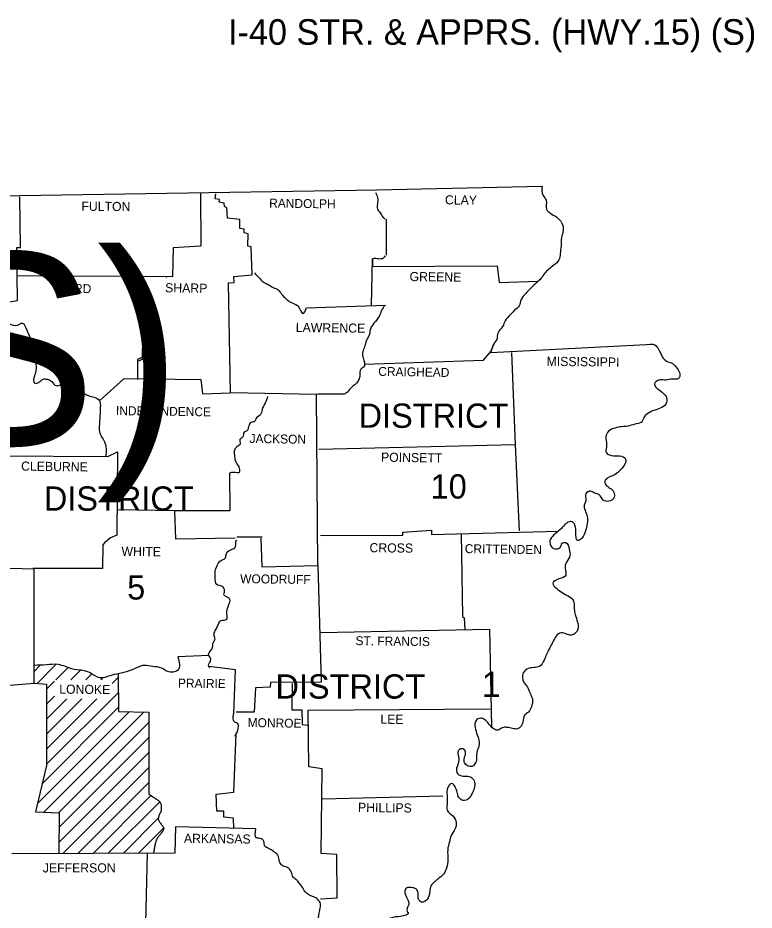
# Model space of a CAD drawing. Extents: x 1127717 to 1741049, y 2026793 to 2244711.
# Drawn here: x 1371845 to 1389121, y 2132784 to 2153727 of the extents above; entities that cross this region are included whole.
import ezdxf

# ---------------------------------------------------------------- set-up
doc = ezdxf.new("R2010")
doc.units = 0
doc.layers.add('1', color=7, linetype='Continuous')
doc.layers.add('R_Draft', color=7, linetype='Continuous')

msp = doc.modelspace()

# ---------------------------------------------------------------- linework, layer by layer
at = {"layer": 'R_Draft'}
for p, q in [((1380455, 2146979), (1380470, 2146984)), ((1382945, 2145874), (1383005, 2146059)), ((1382960, 2145934), (1383020, 2146079)), ((1376985, 2141544), (1377580, 2141544)), ((1372225, 2138388), (1372371, 2138534)), ((1372295, 2138105), (1372738, 2138548)), ((1372736, 2138192), (1373023, 2138480)), ((1373089, 2138192), (1373314, 2138417)), ((1373443, 2138192), (1373582, 2138331)), ((1372515, 2137971), (1372704, 2138160)), ((1373796, 2138192), (1373848, 2138243)), ((1374060, 2138102), (1374201, 2138243)), ((1372520, 2136208), (1374205, 2137893)), ((1372516, 2137619), (1372704, 2137807)), ((1372517, 2137266), (1372993, 2137742)), ((1372518, 2136914), (1373346, 2137742)), ((1372519, 2136561), (1373700, 2137742)), ((1372306, 2135287), (1374458, 2137439)), ((1372417, 2135752), (1374209, 2137544)), ((1372458, 2135086), (1374804, 2137432)), ((1372796, 2135070), (1374915, 2137190)), ((1372813, 2134734), (1374916, 2136837)), ((1372811, 2134378), (1374917, 2136484)), ((1372900, 2134114), (1374918, 2136132)), ((1373255, 2134116), (1374919, 2135779)), ((1373610, 2134117), (1374969, 2135476)), ((1373965, 2134118), (1375173, 2135326)), ((1374320, 2134120), (1375141, 2134940)), ((1374675, 2134121), (1375268, 2134714)), ((1375030, 2134122), (1375031, 2134123))]:
    msp.add_line(p, q, dxfattribs=at)
for points in [[(1356715, 2149549), (1364800, 2149544), (1371895, 2149559), (1380265, 2149689), (1384145, 2149779)], [(1376130, 2149604), (1376140, 2148364), (1375490, 2148329), (1375470, 2147649), (1371855, 2147669)], [(1377545, 2141514), (1377570, 2140839), (1378885, 2140874), (1378850, 2144884), (1376835, 2144929), (1376790, 2147509), (1376920, 2147514), (1376915, 2147654), (1377340, 2147694), (1377320, 2148349), (1377240, 2148364), (1377245, 2148654), (1377155, 2148679), (1377155, 2148764), (1377050, 2148779), (1377050, 2148994), (1376765, 2149024), (1376750, 2149264), (1376695, 2149299), (1376685, 2149379), (1376570, 2149404), (1376575, 2149464), (1376475, 2149479), (1376490, 2149599)], [(1370380, 2137464), (1371505, 2137469), (1371555, 2138059), (1372225, 2138109), (1372225, 2140789), (1371375, 2140814), (1371390, 2143449), (1370320, 2143519), (1370305, 2144699), (1370270, 2144759), (1370300, 2145499), (1370920, 2145519), (1370945, 2146129), (1371625, 2146154), (1371635, 2146549), (1371515, 2146704), (1371485, 2147039), (1371835, 2147089), (1371820, 2148334), (1371905, 2148339), (1371895, 2149529)], [(1380485, 2148999), (1380485, 2148154)], [(1380143, 2146973), (1380170, 2148074), (1380170, 2147889), (1383095, 2147904), (1383135, 2147514), (1384053, 2147548)], [(1374700, 2147634), (1374690, 2147344), (1374830, 2147334), (1374835, 2147014), (1374785, 2147014), (1374765, 2145754), (1374650, 2145704), (1374650, 2145284)], [(1374700, 2147589), (1374690, 2147299), (1374830, 2147289), (1374835, 2146969), (1374785, 2146969), (1374765, 2145709), (1374650, 2145659), (1374650, 2145239)], [(1375325, 2147624), (1375330, 2147629)], [(1378615, 2146919), (1380470, 2146984)], [(1382945, 2145874), (1386740, 2146069)], [(1379970, 2145599), (1382770, 2145689), (1382953, 2145901)], [(1383425, 2145869), (1383510, 2143704), (1383610, 2141689)], [(1373770, 2144749), (1374340, 2145264), (1376140, 2145239), (1376175, 2144904), (1376830, 2144929)], [(1379505, 2144894), (1378895, 2144894), (1378850, 2144884)], [(1371390, 2143449), (1373960, 2143434), (1374180, 2143539), (1374165, 2141584), (1374015, 2141519), (1373880, 2141404), (1373835, 2141359), (1373830, 2140799), (1372195, 2140799)], [(1383510, 2143704), (1378905, 2143599)], [(1376810, 2143039), (1376820, 2142159), (1375520, 2142154), (1374185, 2142179)], [(1375520, 2142154), (1375540, 2141499), (1376945, 2141524)], [(1378945, 2141574), (1380875, 2141584), (1380880, 2141654), (1381550, 2141704), (1381550, 2141599), (1384528, 2141681)], [(1376985, 2141459), (1376960, 2141454)], [(1382249, 2141619), (1382275, 2139674), (1382320, 2139644), (1382336, 2139368)], [(1378885, 2140874), (1378960, 2138134), (1377770, 2138129), (1377765, 2138019), (1377420, 2137999), (1377390, 2137429), (1376970, 2137429)], [(1378945, 2139299), (1382915, 2139379)], [(1382915, 2139379), (1382957, 2137089)], [(1376325, 2138764), (1375600, 2138729)], [(1376915, 2137404), (1376950, 2138424), (1376325, 2138504)], [(1374200, 2138333), (1374210, 2137444), (1374915, 2137429), (1374920, 2135509)], [(1372225, 2138109), (1372515, 2138089), (1372520, 2136179), (1372260, 2135094), (1372815, 2135069), (1372810, 2134114)], [(1378280, 2138104), (1378275, 2137484), (1378505, 2137484), (1378515, 2137139), (1378660, 2137124)], [(1378945, 2133049), (1379335, 2133074), (1379330, 2134089), (1378965, 2134114), (1378985, 2136099), (1378670, 2136144), (1378660, 2137479), (1382925, 2137509)], [(1376912, 2134703), (1376905, 2134944), (1376680, 2134969), (1376675, 2135109), (1376510, 2135104), (1376500, 2135509), (1376910, 2135554), (1376970, 2136924)], [(1378995, 2135394), (1381815, 2135464)], [(1377430, 2134689), (1375540, 2134739), (1375530, 2134124), (1371705, 2134109)], [(1374876, 2134122), (1374835, 2132159), (1375530, 2132104)]]:
    msp.add_lwpolyline(points, dxfattribs=at)
for points in [[(1380240, 2149624), (1380285, 2149499), (1380280, 2149364), (1380280, 2149239), (1380345, 2149154), (1380410, 2149049), (1380460, 2149004)], [(1384145, 2149779), (1384170, 2149559), (1384240, 2149444), (1384250, 2149234), (1384335, 2149144), (1384480, 2149054), (1384610, 2148909), (1384640, 2148739), (1384600, 2148564), (1384590, 2148369), (1384570, 2148199), (1384540, 2148044), (1384420, 2147919), (1384305, 2147829), (1384200, 2147724), (1384125, 2147614), (1383995, 2147494), (1383865, 2147369), (1383760, 2147259), (1383655, 2147119), (1383605, 2146964), (1383490, 2146854), (1383400, 2146754), (1383280, 2146619), (1383220, 2146484), (1383105, 2146329), (1383080, 2146179), (1383005, 2146059), (1383000, 2146039)], [(1384145, 2149779), (1384170, 2149559), (1384240, 2149444), (1384250, 2149234), (1384335, 2149144), (1384480, 2149054), (1384610, 2148909), (1384640, 2148739), (1384600, 2148564), (1384590, 2148369), (1384570, 2148199), (1384540, 2148044), (1384420, 2147919), (1384305, 2147829), (1384200, 2147724), (1384125, 2147614), (1383995, 2147494), (1383865, 2147369), (1383760, 2147259), (1383655, 2147119), (1383605, 2146964), (1383490, 2146854), (1383400, 2146754), (1383280, 2146619), (1383220, 2146484), (1383105, 2146329), (1383080, 2146179), (1383005, 2146059), (1383000, 2146039)], [(1380465, 2148139), (1380400, 2148074), (1380275, 2148074), (1380170, 2148074)], [(1377395, 2147739), (1377505, 2147624), (1377600, 2147529), (1377710, 2147474), (1377840, 2147399), (1377955, 2147339), (1378030, 2147244), (1378135, 2147139), (1378240, 2147054), (1378405, 2146974), (1378460, 2146889), (1378535, 2146784), (1378615, 2146919)], [(1380455, 2146979), (1380380, 2146859), (1380320, 2146719), (1380200, 2146559), (1380110, 2146404), (1380095, 2146299), (1380025, 2146159), (1379985, 2146019), (1379940, 2145899), (1379940, 2145774), (1379975, 2145649), (1379965, 2145534), (1379890, 2145479), (1379870, 2145334), (1379840, 2145234), (1379775, 2145134), (1379680, 2145059), (1379580, 2144944), (1379505, 2144894)], [(1371635, 2146549), (1371835, 2146514), (1371955, 2146559), (1372040, 2146429), (1372085, 2146329), (1372160, 2146184), (1372280, 2146139), (1372370, 2146059), (1372370, 2145974), (1372290, 2145894), (1372230, 2145814), (1372250, 2145719), (1372270, 2145589), (1372270, 2145464), (1372240, 2145349), (1372215, 2145244), (1372240, 2145154), (1372335, 2145169), (1372435, 2145244), (1372540, 2145244), (1372640, 2145189), (1372745, 2145094), (1372850, 2145114), (1372935, 2145139), (1373055, 2145174), (1373140, 2145129), (1373215, 2145069), (1373305, 2144974), (1373390, 2144914), (1373500, 2144859), (1373635, 2144824), (1373760, 2144739), (1373780, 2144594), (1373775, 2144469), (1373765, 2144314), (1373755, 2144144), (1373770, 2143979), (1373825, 2143869), (1373895, 2143739), (1373915, 2143619), (1373910, 2143429)], [(1386685, 2146064), (1386740, 2146069), (1386910, 2145889), (1386985, 2145739), (1387095, 2145654), (1387220, 2145609), (1387315, 2145494), (1387380, 2145369), (1387345, 2145259), (1387205, 2145249), (1387050, 2145224), (1386900, 2145229), (1386780, 2145129), (1386890, 2144994), (1387035, 2144869), (1387075, 2144734), (1386995, 2144604), (1386835, 2144534), (1386680, 2144474), (1386540, 2144354), (1386475, 2144239), (1386320, 2144189), (1386160, 2144144), (1386020, 2144129), (1385860, 2144099), (1385705, 2144024), (1385640, 2143894), (1385660, 2143709), (1385655, 2143514), (1385820, 2143449), (1385965, 2143444), (1386105, 2143369), (1386090, 2143259), (1385985, 2143119), (1385860, 2143009), (1385735, 2142954), (1385620, 2142849), (1385660, 2142744), (1385765, 2142674), (1385840, 2142559), (1385830, 2142454), (1385710, 2142379), (1385580, 2142409), (1385485, 2142534), (1385375, 2142574), (1385280, 2142619), (1385170, 2142554), (1385170, 2142409), (1385130, 2142254), (1385165, 2142139), (1385210, 2141979), (1385205, 2141859), (1385165, 2141689), (1385080, 2141514), (1384980, 2141459), (1384940, 2141649), (1384920, 2141804), (1384860, 2141894), (1384780, 2141899), (1384675, 2141824), (1384560, 2141709), (1384415, 2141584), (1384330, 2141459), (1384375, 2141304), (1384485, 2141264), (1384570, 2141294), (1384615, 2141394), (1384700, 2141409), (1384780, 2141254)], [(1386685, 2146064), (1386740, 2146069), (1386910, 2145889), (1386985, 2145739), (1387095, 2145654), (1387220, 2145609), (1387315, 2145494), (1387380, 2145369), (1387345, 2145259), (1387205, 2145249), (1387050, 2145224), (1386900, 2145229), (1386780, 2145129), (1386890, 2144994), (1387035, 2144869), (1387075, 2144734), (1386995, 2144604), (1386835, 2144534), (1386680, 2144474), (1386540, 2144354), (1386475, 2144239), (1386320, 2144189), (1386160, 2144144), (1386020, 2144129), (1385860, 2144099), (1385705, 2144024), (1385640, 2143894), (1385660, 2143709), (1385655, 2143514), (1385820, 2143449), (1385965, 2143444), (1386105, 2143369), (1386090, 2143259), (1385985, 2143119), (1385860, 2143009), (1385735, 2142954), (1385620, 2142849), (1385660, 2142744), (1385765, 2142674), (1385840, 2142559), (1385830, 2142454), (1385710, 2142379), (1385580, 2142409), (1385485, 2142534), (1385375, 2142574), (1385280, 2142619), (1385170, 2142554), (1385170, 2142409), (1385130, 2142254), (1385165, 2142139), (1385210, 2141979), (1385205, 2141859), (1385165, 2141689), (1385080, 2141514), (1384980, 2141459), (1384940, 2141649), (1384920, 2141804), (1384860, 2141894), (1384780, 2141899), (1384675, 2141824), (1384560, 2141709), (1384415, 2141584), (1384330, 2141459), (1384375, 2141304), (1384485, 2141264), (1384570, 2141294), (1384615, 2141394), (1384700, 2141409), (1384780, 2141254)], [(1377705, 2144839), (1377645, 2144684), (1377575, 2144534), (1377530, 2144404), (1377435, 2144329), (1377405, 2144259), (1377320, 2144229), (1377255, 2144129), (1377225, 2144039), (1377155, 2143999), (1377120, 2143889), (1377055, 2143829), (1377060, 2143729), (1376985, 2143659), (1376925, 2143579), (1376925, 2143469), (1376950, 2143324), (1377000, 2143239), (1377045, 2143129), (1377040, 2143059), (1376915, 2143059), (1376810, 2143039)], [(1376350, 2138469), (1376325, 2138504), (1376355, 2138614), (1376370, 2138684), (1376320, 2138784), (1376365, 2138869), (1376415, 2138959), (1376430, 2139064), (1376470, 2139134), (1376455, 2139224), (1376475, 2139349), (1376530, 2139444), (1376610, 2139579), (1376745, 2139614), (1376755, 2139669), (1376750, 2139794), (1376805, 2139979), (1376825, 2140044), (1376805, 2140104), (1376685, 2140174), (1376695, 2140279), (1376635, 2140379), (1376510, 2140424), (1376475, 2140594), (1376475, 2140744), (1376530, 2140889), (1376615, 2140994), (1376705, 2141034), (1376730, 2141134), (1376840, 2141244), (1376935, 2141289), (1376960, 2141454)], [(1384780, 2141254), (1384800, 2141109), (1384715, 2140954), (1384685, 2140799), (1384700, 2140644), (1384540, 2140559), (1384400, 2140459), (1384480, 2140339), (1384630, 2140229), (1384780, 2140144), (1384875, 2140059), (1384900, 2139854), (1384925, 2139724), (1384975, 2139544), (1384995, 2139419), (1384905, 2139269), (1384800, 2139239), (1384690, 2139274), (1384560, 2139284), (1384455, 2139184), (1384380, 2139044), (1384305, 2138904), (1384250, 2138784), (1384195, 2138654), (1384085, 2138504), (1383950, 2138479), (1383790, 2138439), (1383695, 2138329), (1383710, 2138144), (1383800, 2138019), (1383870, 2137864), (1383920, 2137729), (1383895, 2137559), (1383825, 2137434), (1383735, 2137359), (1383695, 2137199), (1383630, 2137079), (1383570, 2137039), (1383450, 2137049), (1383320, 2137074), (1383210, 2137064), (1383105, 2137009), (1383000, 2137044), (1382890, 2137164), (1382800, 2137254), (1382700, 2137289), (1382595, 2137234), (1382575, 2137069), (1382625, 2136899), (1382670, 2136669), (1382625, 2136529), (1382610, 2136299)], [(1384780, 2141254), (1384800, 2141109), (1384715, 2140954), (1384685, 2140799), (1384700, 2140644), (1384540, 2140559), (1384400, 2140459), (1384480, 2140339), (1384630, 2140229), (1384780, 2140144), (1384875, 2140059), (1384900, 2139854), (1384925, 2139724), (1384975, 2139544), (1384995, 2139419), (1384905, 2139269), (1384800, 2139239), (1384690, 2139274), (1384560, 2139284), (1384455, 2139184), (1384380, 2139044), (1384305, 2138904), (1384250, 2138784), (1384195, 2138654), (1384085, 2138504), (1383950, 2138479), (1383790, 2138439), (1383695, 2138329), (1383710, 2138144), (1383800, 2138019), (1383870, 2137864), (1383920, 2137729), (1383895, 2137559), (1383825, 2137434), (1383735, 2137359), (1383695, 2137199), (1383630, 2137079), (1383570, 2137039), (1383450, 2137049), (1383320, 2137074), (1383210, 2137064), (1383105, 2137009), (1383000, 2137044), (1382890, 2137164), (1382800, 2137254), (1382700, 2137289), (1382595, 2137234), (1382575, 2137069), (1382625, 2136899), (1382670, 2136669), (1382625, 2136529), (1382610, 2136299)], [(1375600, 2138729), (1375600, 2138419), (1375355, 2138384), (1375220, 2138464), (1375005, 2138504), (1374815, 2138529), (1374625, 2138469), (1374460, 2138399), (1374205, 2138334), (1374010, 2138284), (1373760, 2138239), (1373565, 2138339), (1373400, 2138404), (1373165, 2138434), (1372965, 2138499), (1372790, 2138549), (1372515, 2138539), (1372225, 2138529)], [(1376925, 2136864), (1376970, 2136924), (1376990, 2136964), (1377015, 2137064), (1377005, 2137164), (1376935, 2137199), (1376895, 2137304), (1376915, 2137404)], [(1382610, 2136299), (1382495, 2136154), (1382325, 2136244), (1382325, 2136364), (1382350, 2136489), (1382290, 2136569), (1382185, 2136534), (1382185, 2136379), (1382175, 2136229), (1382145, 2136014), (1382215, 2135949), (1382375, 2135929), (1382490, 2135899), (1382560, 2135784), (1382555, 2135644), (1382500, 2135509), (1382420, 2135399), (1382295, 2135359), (1382195, 2135424), (1382155, 2135554), (1382110, 2135669), (1382025, 2135754), (1381935, 2135659), (1381915, 2135484), (1381920, 2135334), (1381920, 2135129), (1382050, 2134994), (1382130, 2134839), (1382105, 2134699), (1382010, 2134534), (1381970, 2134389), (1381930, 2134194), (1381935, 2133979), (1381900, 2133769), (1381830, 2133629), (1381700, 2133514), (1381615, 2133439), (1381545, 2133364), (1381510, 2133214), (1381485, 2133109), (1381390, 2132984), (1381315, 2132974), (1381255, 2133024), (1381235, 2133109), (1381235, 2133194), (1381195, 2133279), (1381070, 2133314), (1380970, 2133309), (1380925, 2133239), (1380990, 2133044), (1381015, 2132919), (1380980, 2132749), (1381000, 2132729), (1380820, 2132634), (1380675, 2132619), (1380555, 2132584), (1380440, 2132509), (1380385, 2132399), (1380305, 2132309), (1380235, 2132224), (1380140, 2132184), (1380035, 2132204), (1379895, 2132219), (1379815, 2132119), (1379840, 2131974), (1379935, 2131889), (1380075, 2131849), (1380220, 2131859), (1380360, 2131874), (1380490, 2131804), (1380465, 2131669), (1380340, 2131604), (1380155, 2131584), (1380005, 2131599), (1379825, 2131559), (1379735, 2131444), (1379785, 2131269), (1379980, 2131199), (1380070, 2131034), (1380075, 2130879), (1380010, 2130674), (1379920, 2130579), (1379745, 2130539), (1379610, 2130514), (1379590, 2130284), (1379530, 2130169), (1379425, 2130134), (1379275, 2130209), (1379185, 2130244), (1379075, 2130294), (1378935, 2130379), (1378830, 2130364), (1378860, 2130144), (1378870, 2130134), (1378990, 2129969), (1379110, 2129839), (1379165, 2129684)], [(1382610, 2136299), (1382495, 2136154), (1382325, 2136244), (1382325, 2136364), (1382350, 2136489), (1382290, 2136569), (1382185, 2136534), (1382185, 2136379), (1382175, 2136229), (1382145, 2136014), (1382215, 2135949), (1382375, 2135929), (1382490, 2135899), (1382560, 2135784), (1382555, 2135644), (1382500, 2135509), (1382420, 2135399), (1382295, 2135359), (1382195, 2135424), (1382155, 2135554), (1382110, 2135669), (1382025, 2135754), (1381935, 2135659), (1381915, 2135484), (1381920, 2135334), (1381920, 2135129), (1382050, 2134994), (1382130, 2134839), (1382105, 2134699), (1382010, 2134534), (1381970, 2134389), (1381930, 2134194), (1381935, 2133979), (1381900, 2133769), (1381830, 2133629), (1381700, 2133514), (1381615, 2133439), (1381545, 2133364), (1381510, 2133214), (1381485, 2133109), (1381390, 2132984), (1381315, 2132974), (1381255, 2133024), (1381235, 2133109), (1381235, 2133194), (1381195, 2133279), (1381070, 2133314), (1380970, 2133309), (1380925, 2133239), (1380990, 2133044), (1381015, 2132919), (1380980, 2132749), (1381000, 2132729), (1380820, 2132634), (1380675, 2132619), (1380555, 2132584), (1380440, 2132509), (1380385, 2132399), (1380305, 2132309), (1380235, 2132224), (1380140, 2132184), (1380035, 2132204), (1379895, 2132219), (1379815, 2132119), (1379840, 2131974), (1379935, 2131889), (1380075, 2131849), (1380220, 2131859), (1380360, 2131874), (1380490, 2131804), (1380465, 2131669), (1380340, 2131604), (1380155, 2131584), (1380005, 2131599), (1379825, 2131559), (1379735, 2131444), (1379785, 2131269), (1379980, 2131199), (1380070, 2131034), (1380075, 2130879), (1380010, 2130674), (1379920, 2130579), (1379745, 2130539), (1379610, 2130514), (1379590, 2130284), (1379530, 2130169), (1379425, 2130134), (1379275, 2130209), (1379185, 2130244), (1379075, 2130294), (1378935, 2130379), (1378830, 2130364), (1378860, 2130144), (1378870, 2130134), (1378990, 2129969), (1379110, 2129839), (1379165, 2129684)], [(1374920, 2135509), (1375045, 2135424), (1375078, 2135402), (1375111, 2135380), (1375144, 2135355), (1375159, 2135341), (1375167, 2135333), (1375175, 2135324), (1375195, 2135293), (1375205, 2135260), (1375208, 2135224), (1375209, 2135207), (1375210, 2135189), (1375210, 2135166), (1375208, 2135142), (1375205, 2135118), (1375200, 2135094), (1375191, 2135074), (1375180, 2135054), (1375169, 2135035), (1375160, 2135014), (1375150, 2134984), (1375142, 2134951), (1375150, 2134889), (1375157, 2134878), (1375164, 2134866), (1375179, 2134844), (1375210, 2134799), (1375224, 2134781), (1375239, 2134762), (1375259, 2134734), (1375262, 2134729), (1375265, 2134724), (1375269, 2134692), (1375256, 2134658), (1375233, 2134623), (1375221, 2134606), (1375210, 2134589), (1375198, 2134573), (1375186, 2134557), (1375160, 2134528), (1375135, 2134498), (1375124, 2134482), (1375115, 2134464), (1375099, 2134431), (1375085, 2134396), (1375065, 2134324), (1375055, 2134274), (1375047, 2134224), (1375031, 2134122)], [(1378700, 2131434), (1378765, 2131514), (1378810, 2131669), (1378830, 2131764), (1378845, 2131929), (1378850, 2132039), (1378900, 2132119), (1378925, 2132269), (1378880, 2132369), (1378890, 2132489), (1378900, 2132624), (1378920, 2132744), (1378945, 2132859), (1378945, 2132934), (1378880, 2133034), (1378780, 2133099), (1378700, 2133124), (1378650, 2133159), (1378580, 2133219), (1378510, 2133339), (1378470, 2133384), (1378390, 2133489), (1378310, 2133549), (1378260, 2133684), (1378180, 2133779), (1378070, 2133819), (1377990, 2133904), (1377960, 2134034), (1377910, 2134114), (1377840, 2134164), (1377725, 2134234), (1377640, 2134284), (1377615, 2134399), (1377565, 2134454), (1377445, 2134484), (1377430, 2134689)]]:
    msp.add_spline(points, degree=3, dxfattribs=at)

# ---------------------------------------------------------------- texts
at = {"layer": '1'}
msp.add_text('I-40 STR. & APPRS. (HWY.15) (S)', height=600, dxfattribs=at).set_placement((1376777, 2153095))
at = {"layer": 'R_Draft'}
for s, height, rotation, p in [('FULTON', 215, 359.4996, (1373335, 2149199)), ('RANDOLPH', 210, 359.2583, (1377740, 2149274)), ('CLAY', 215, 359.2258, (1381865, 2149349)), ('GREENE', 215, 359.2361, (1381035, 2147549)), ('SHARP', 215, 359.3905, (1375300, 2147284)), ('IZARD', 210, 358.9258, (1372725, 2147279)), ('LAWRENCE', 215, 359.2678, (1378365, 2146354)), ('MISSISSIPPI', 214.98, 359.3097, (1384250, 2145559)), ('CRAIGHEAD', 210, 359.1159, (1380300, 2145324)), ('INDEPENDENCE', 209.97, 359.2187, (1374145, 2144404)), ('JACKSON', 210, 359.1352, (1377280, 2143749)), ('POINSETT', 215, 359.1987, (1380365, 2143309)), ('CLEBURNE', 215, 359.2535, (1371920, 2143099)), ('WHITE', 215, 359.3139, (1374275, 2141099)), ('CROSS', 215, 359.3839, (1380095, 2141184)), ('CRITTENDEN', 210, 359.213, (1382330, 2141164)), ('WOODRUFF', 210, 359.2748, (1377060, 2140459)), ('ST. FRANCIS', 209.97, 359.2216, (1379765, 2139004)), ('LONOKE', 215, 359.4974, (1372815, 2137864)), ('PRAIRIE', 210, 359.2116, (1375600, 2138009)), ('MONROE', 210, 359.0331, (1377235, 2137084)), ('LEE', 215, 359.4327, (1380350, 2137159)), ('PHILLIPS', 215, 359.3179, (1379825, 2135089)), ('ARKANSAS', 215, 359.2678, (1375740, 2134364))]:
    msp.add_text(s, height=height, rotation=rotation, dxfattribs=at).set_placement(p)
for s, height, p in [('I-40 STR. & APPRS. (HWY. 15) (S)', 4500, (1281068, 2143713)), ('DISTRICT', 570, (1379840, 2144104)), ('10', 570, (1381530, 2142444)), ('DISTRICT', 570, (1372455, 2142159)), ('5', 570, (1374410, 2140074)), ('DISTRICT', 570, (1377890, 2137749)), ('1', 600, (1382730, 2137784)), ('JEFFERSON', 215, (1372430, 2133669))]:
    msp.add_text(s, height=height, dxfattribs=at).set_placement(p)

doc.saveas('drawing.dxf')
